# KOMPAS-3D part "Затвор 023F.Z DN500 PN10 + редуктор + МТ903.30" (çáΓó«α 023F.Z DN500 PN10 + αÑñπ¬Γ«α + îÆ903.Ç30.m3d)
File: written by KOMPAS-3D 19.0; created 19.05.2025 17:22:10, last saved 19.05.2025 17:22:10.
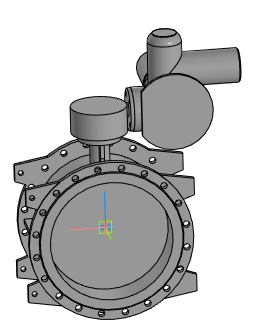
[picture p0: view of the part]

Document properties: Полное имя файла: Затвор 023F.Z DN500 PN10 + редуктор + МТ903.30.a3d

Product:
- Part/product: Затвор 023F.Z DN500 PN10 + редуктор + МТ903.30
    Масса: 425.552

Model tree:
1. Операция без истории:1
